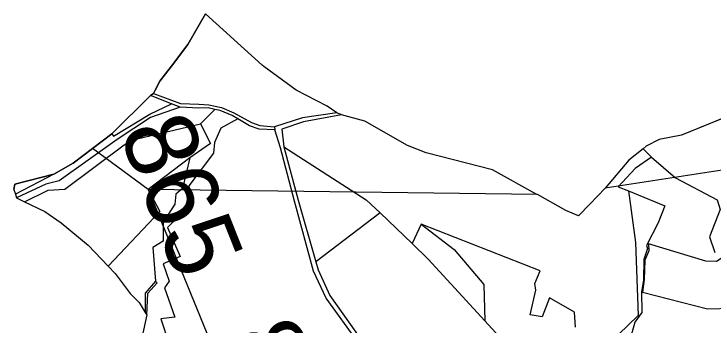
# Model space of a CAD drawing. Extents: x -689422 to -684666, y -987725 to -982160.
# Drawn here: x -689422 to -688518, y -982561 to -982160 of the extents above; entities that cross this region are included whole.
import ezdxf

# ---------------------------------------------------------------- set-up
doc = ezdxf.new("R2010")
doc.units = 0
for name, color, linetype in [('Dalkovy migracni koridor', 7, 'Continuous'), ('Dalkovy migracni koridor popis', 7, 'Continuous'), ('Hranice obce', 7, 'Continuous'), ('KN_Hranice_katastrální území', 7, 'Continuous'), ('KN_hranice_parcel', 7, 'Continuous'), ('Krajina lesozemedelska - 5M2', 7, 'Continuous'), ('Migracne vyznamne uzemi', 7, 'Continuous')]:
    doc.layers.add(name, color=color, linetype=linetype)

msp = doc.modelspace()

# ---------------------------------------------------------------- linework, layer by layer
at = {"layer": 'Dalkovy migracni koridor'}
for p, q in [((-689248.07, -982386.61), (-689320.15, -982333.48)), ((-688745.22, -982393.07), (-689248.07, -982386.61))]:
    msp.add_line(p, q, dxfattribs=at)
for points in [[(-687882.21, -982490.81), (-688366.31, -982339.93), (-688657.8, -982384.57)], [(-689248.07, -982386.61), (-689050.38, -982869.9), (-689019.53, -982977.86), (-688975.65, -983189.91)]]:
    msp.add_lwpolyline(points, dxfattribs=at)
at = {"layer": 'Hranice obce'}
msp.add_lwpolyline([(-688479.99, -982283.8), (-688559.06, -982316.44), (-688587.88, -982321.86), (-688604.6, -982330.69), (-688608.5, -982333.76), (-688627.21, -982348.47), (-688657.8, -982384.57), (-688677.55, -982405.23), (-688692.2, -982420.56), (-688708.5, -982413.35), (-688745.22, -982393.07), (-688745.91, -982392.69), (-688803.08, -982360.91), (-688888.91, -982338.93), (-688912.92, -982329.6), (-688968.34, -982298.26), (-688998.46, -982289.93), (-688998.95, -982289.75), (-689002.89, -982288.29), (-689004.57, -982287.67), (-689016.75, -982279.03), (-689057.02, -982258.22), (-689098.59, -982227.73), (-689100.73, -982225.8), (-689174.07, -982159.87), (-689196.83, -982199.46), (-689218.2, -982227.18), (-689225.83, -982237.08), (-689233.27, -982246.73), (-689239.33, -982258.4), (-689241.08, -982261.77), (-689241.54, -982262.66), (-689245.4, -982264.94), (-689295.33, -982314.65), (-689344.96, -982352.3), (-689370.15, -982366.54), (-689420.52, -982379.61), (-689421.63, -982386.24), (-689419.65, -982392.62), (-689418.16, -982397.39), (-689408.17, -982402.2), (-689381.97, -982414.81), (-689360.72, -982429.64), (-689325.69, -982458.08), (-689299.97, -982485.18), (-689290.84, -982494.81), (-689271.64, -982520.72), (-689259.92, -982532.32), (-689252.18, -982545.1), (-689250.16, -982548.42), (-689263.67, -982611.26)], dxfattribs=at)
at = {"layer": 'KN_Hranice_katastrální území'}
msp.add_lwpolyline([(-688479.99, -982283.8), (-688559.06, -982316.44), (-688587.88, -982321.86), (-688604.6, -982330.69), (-688608.5, -982333.76), (-688627.21, -982348.47), (-688657.8, -982384.57), (-688677.55, -982405.23), (-688692.2, -982420.56), (-688708.5, -982413.35), (-688745.22, -982393.07), (-688745.91, -982392.69), (-688803.08, -982360.91), (-688888.91, -982338.93), (-688912.92, -982329.6), (-688968.34, -982298.26), (-688998.46, -982289.93), (-688998.95, -982289.75), (-689002.89, -982288.29), (-689004.57, -982287.67), (-689016.75, -982279.03), (-689057.02, -982258.22), (-689098.59, -982227.73), (-689100.73, -982225.8), (-689174.07, -982159.87), (-689196.83, -982199.46), (-689218.2, -982227.18), (-689225.83, -982237.08), (-689233.27, -982246.73), (-689239.33, -982258.4), (-689241.08, -982261.77), (-689241.54, -982262.66), (-689245.4, -982264.94), (-689295.33, -982314.65), (-689344.96, -982352.3), (-689370.15, -982366.54), (-689420.52, -982379.61), (-689421.63, -982386.24), (-689419.65, -982392.62), (-689418.16, -982397.39), (-689408.17, -982402.2), (-689381.97, -982414.81), (-689360.72, -982429.64), (-689325.69, -982458.08), (-689299.97, -982485.18), (-689290.84, -982494.81), (-689271.64, -982520.72), (-689259.92, -982532.32), (-689252.18, -982545.1), (-689250.16, -982548.42), (-689263.67, -982611.26)], dxfattribs=at)
at = {"layer": 'KN_hranice_parcel'}
for p, q in [((-689100.73, -982225.8), (-689174.07, -982159.87)), ((-689225.83, -982237.08), (-689218.2, -982227.18)), ((-689295.33, -982314.65), (-689245.4, -982264.94)), ((-689245.4, -982264.94), (-689241.54, -982262.66)), ((-689217.89, -982275.98), (-689245.4, -982264.94)), ((-689241.54, -982262.66), (-689206.31, -982275.42)), ((-689207.09, -982280.31), (-689217.89, -982275.98)), ((-689161.88, -982283.06), (-689180.48, -982301.54)), ((-689161.88, -982283.06), (-689170.73, -982281.16)), ((-689155.06, -982284.52), (-689161.88, -982283.06)), ((-689139.79, -982290.9), (-689155.06, -982284.52)), ((-689002.89, -982288.29), (-689004.57, -982287.67)), ((-688479.99, -982283.8), (-688559.06, -982316.44)), ((-689132.3, -982295.35), (-689139.79, -982290.9)), ((-689117.13, -982304.36), (-689132.3, -982295.35)), ((-688998.95, -982289.75), (-689002.89, -982288.29)), ((-688998.46, -982289.93), (-688998.95, -982289.75)), ((-689085.13, -982305.51), (-689084.54, -982309.35)), ((-689073, -982331.34), (-689054.22, -982400.25)), ((-688604.6, -982330.69), (-688608.5, -982333.76)), ((-688803.08, -982360.91), (-688888.91, -982338.93)), ((-688608.5, -982333.76), (-688597.66, -982344.88)), ((-689420.52, -982379.61), (-689370.15, -982366.54)), ((-689370.15, -982366.54), (-689419.65, -982392.62)), ((-688745.91, -982392.69), (-688803.08, -982360.91)), ((-689421.63, -982386.24), (-689420.52, -982379.61)), ((-689421.63, -982386.24), (-689419.65, -982392.62)), ((-689419.65, -982392.62), (-689418.16, -982397.39)), ((-688745.22, -982393.07), (-688745.91, -982392.69)), ((-688708.5, -982413.35), (-688745.22, -982393.07)), ((-689418.16, -982397.39), (-689408.17, -982402.2)), ((-689408.17, -982402.2), (-689381.97, -982414.81)), ((-689054.22, -982400.25), (-689031.44, -982479.99)), ((-688677.55, -982405.23), (-688692.2, -982420.56)), ((-688692.2, -982420.56), (-688708.5, -982413.35)), ((-688948.64, -982416.69), (-689031.44, -982479.99)), ((-688907.18, -982456.28), (-688948.64, -982416.69)), ((-688895.28, -982431), (-688907.18, -982456.28)), ((-689325.69, -982458.08), (-689299.97, -982485.18)), ((-689299.97, -982485.18), (-689290.84, -982494.81)), ((-689031.44, -982479.99), (-689028.56, -982490.08)), ((-688609.32, -982518.77), (-688610.88, -982518.36)), ((-689252.18, -982545.1), (-689250.16, -982548.42)), ((-688813.31, -982555.94), (-688794.65, -982576.32))]:
    msp.add_line(p, q, dxfattribs=at)
for points in [[(-689218.2, -982227.18), (-689196.83, -982199.46), (-689174.07, -982159.87)], [(-689004.57, -982287.67), (-689016.75, -982279.03), (-689057.02, -982258.22), (-689098.59, -982227.73), (-689100.73, -982225.8)], [(-689241.54, -982262.66), (-689241.08, -982261.77), (-689239.33, -982258.4), (-689233.27, -982246.73), (-689225.83, -982237.08)], [(-689295.33, -982314.65), (-689293.24, -982317.45), (-689246.03, -982289.03), (-689217.89, -982275.98)], [(-689206.31, -982275.42), (-689182.81, -982276.06), (-689169.97, -982277.14), (-689153.67, -982280.7), (-689137.74, -982287.53), (-689114.61, -982300.04), (-689104.07, -982303.87), (-689085.13, -982305.51)], [(-689207.09, -982280.31), (-689245.09, -982293.55), (-689288.16, -982322.06), (-689363.24, -982375.02), (-689380.54, -982379.72), (-689418.16, -982397.39)], [(-689170.73, -982281.16), (-689182.68, -982281.37), (-689207.09, -982280.31)], [(-689004.57, -982287.67), (-689048.75, -982293.75), (-689085.13, -982305.51)], [(-689132.3, -982295.35), (-689154.31, -982307.35), (-689162.48, -982325.88), (-689163.75, -982339.5), (-689195.48, -982381.69), (-689192.3, -982404.85), (-689223.24, -982435.28), (-689206.97, -982472.82), (-689228.68, -982482.32), (-689220.91, -982504.84), (-689227.09, -982513.18), (-689213.95, -982551.11), (-689232.01, -982553.5), (-689220.98, -982586.19), (-689240.9, -982594.56), (-689221.33, -982611.7), (-689223.53, -982619.27), (-689246.1, -982624.55), (-689245.3, -982634.52), (-689249.68, -982633.19), (-689261.24, -982663.02), (-689260.84, -982684.68), (-689274.91, -982699.36), (-689277.87, -982740.23)], [(-688998.46, -982289.93), (-689047.38, -982299.22), (-689075.47, -982308.44), (-689073, -982331.34)], [(-688888.91, -982338.93), (-688912.92, -982329.6), (-688968.34, -982298.26), (-688998.46, -982289.93)], [(-689408.17, -982402.2), (-689377.35, -982387.34), (-689355.91, -982386.12), (-689279.13, -982328.6), (-689269.78, -982322.86), (-689180.48, -982301.54)], [(-689180.48, -982301.54), (-689167.75, -982327.17), (-689194.19, -982345.72)], [(-689084.54, -982309.35), (-689104.97, -982308.38), (-689117.13, -982304.36)], [(-689370.15, -982366.54), (-689344.96, -982352.3), (-689295.33, -982314.65)], [(-688976.63, -982584.53), (-689018.36, -982526.75), (-689034.37, -982491.83), (-689059.15, -982401.37), (-689077.12, -982332.65), (-689084.54, -982309.35)], [(-688559.06, -982316.44), (-688587.88, -982321.86), (-688604.6, -982330.69)], [(-689073, -982331.34), (-688966.58, -982399.56), (-688948.64, -982416.69)], [(-688608.5, -982333.76), (-688627.21, -982348.47), (-688657.8, -982384.57), (-688677.55, -982405.23)], [(-689194.19, -982345.72), (-689248.07, -982386.61), (-689233.02, -982414.94), (-689299.97, -982485.18)], [(-689194.19, -982345.72), (-689203.78, -982385.28), (-689212.44, -982392.62), (-689213.75, -982405.41), (-689228.69, -982428.58), (-689228.69, -982453.33), (-689242.33, -982461.21), (-689238.58, -982504.84)], [(-688597.66, -982344.88), (-688618.84, -982359.45), (-688640.87, -982382.91), (-688627.65, -982388.34)], [(-688597.66, -982344.88), (-688566.97, -982371.29), (-688513.06, -982399.73), (-688509.01, -982412.35), (-688522.88, -982447.63), (-688515.82, -982467.85)], [(-688627.65, -982388.34), (-688618.63, -982454.89), (-688614.92, -982548.98), (-688653.05, -982585.47)], [(-688627.65, -982388.34), (-688580.78, -982407.61), (-688589.37, -982429.54), (-688604.21, -982458.53), (-688602.8, -982462.69), (-688607.54, -982476.96), (-688608.21, -982503.08), (-688610.88, -982518.36)], [(-689381.97, -982414.81), (-689360.72, -982429.64), (-689325.69, -982458.08)], [(-688895.28, -982431), (-688852.67, -982463.96), (-688814.61, -982508.87), (-688813.31, -982555.94)], [(-688696.12, -982564.1), (-688697.51, -982544.63), (-688729.55, -982526.44), (-688738.92, -982550.91), (-688754.73, -982548.13), (-688747.12, -982516.55), (-688748.58, -982507.91), (-688741.7, -982491.57), (-688895.28, -982431)], [(-688907.18, -982456.28), (-688886.34, -982476.18), (-688813.31, -982555.94)], [(-688447.14, -982508.24), (-688448.12, -982491.82), (-688462.64, -982460.26), (-688483.68, -982459.74), (-688513.67, -982479.19), (-688527.78, -982479.06), (-688601.69, -982456.52), (-688601.17, -982465.72), (-688606.21, -982477.63), (-688607.32, -982502.64), (-688609.32, -982518.77)], [(-689290.84, -982494.81), (-689271.64, -982520.72), (-689259.92, -982532.32), (-689252.18, -982545.1)], [(-689028.56, -982490.08), (-689013.39, -982523.42), (-688972.41, -982581.04), (-688935.15, -982614.73), (-688912.49, -982642.6), (-688867.24, -982688.32)], [(-689238.58, -982504.84), (-689252.12, -982520.12), (-689252.18, -982545.1)], [(-689250.16, -982548.42), (-689248.81, -982520.39), (-689236.72, -982506.7), (-689238.58, -982504.84)], [(-688610.88, -982518.36), (-688610.23, -982545.07), (-688619.41, -982557.77), (-688632.32, -982604.47)], [(-688609.32, -982518.77), (-688525.48, -982540.51), (-688494.01, -982539.74)], [(-689250.16, -982548.42), (-689263.67, -982611.26), (-689261.99, -982634.29), (-689268.82, -982654.64)]]:
    msp.add_lwpolyline(points, dxfattribs=at)
at = {"layer": 'Krajina lesozemedelska - 5M2'}
msp.add_lwpolyline([(-688479.99, -982283.8), (-688559.06, -982316.44), (-688587.88, -982321.86), (-688604.6, -982330.69), (-688608.5, -982333.76), (-688627.21, -982348.47), (-688657.8, -982384.57), (-688677.55, -982405.23), (-688692.2, -982420.56), (-688708.5, -982413.35), (-688745.22, -982393.07), (-688745.91, -982392.69), (-688803.08, -982360.91), (-688888.91, -982338.93), (-688912.92, -982329.6), (-688968.34, -982298.26), (-688998.46, -982289.93), (-688998.95, -982289.75), (-689002.89, -982288.29), (-689004.57, -982287.67), (-689016.75, -982279.03), (-689057.02, -982258.22), (-689098.59, -982227.73), (-689100.73, -982225.8), (-689174.07, -982159.87), (-689196.83, -982199.46), (-689218.2, -982227.18), (-689225.83, -982237.08), (-689233.27, -982246.73), (-689239.33, -982258.4), (-689241.08, -982261.77), (-689241.54, -982262.66), (-689245.4, -982264.94), (-689295.33, -982314.65), (-689344.96, -982352.3), (-689370.15, -982366.54), (-689420.52, -982379.61), (-689421.63, -982386.24), (-689419.65, -982392.62), (-689418.16, -982397.39), (-689408.17, -982402.2), (-689381.97, -982414.81), (-689360.72, -982429.64), (-689325.69, -982458.08), (-689299.97, -982485.18), (-689290.84, -982494.81), (-689271.64, -982520.72), (-689259.92, -982532.32), (-689252.18, -982545.1), (-689250.16, -982548.42), (-689263.67, -982611.26)], dxfattribs=at)
at = {"layer": 'Migracne vyznamne uzemi'}
msp.add_lwpolyline([(-688479.99, -982283.8), (-688559.06, -982316.44), (-688587.88, -982321.86), (-688604.6, -982330.69), (-688608.5, -982333.76), (-688627.21, -982348.47), (-688657.8, -982384.57), (-688677.55, -982405.23), (-688692.2, -982420.56), (-688708.5, -982413.35), (-688745.22, -982393.07), (-688745.91, -982392.69), (-688803.08, -982360.91), (-688888.91, -982338.93), (-688912.92, -982329.6), (-688968.34, -982298.26), (-688998.46, -982289.93), (-688998.95, -982289.75), (-689002.89, -982288.29), (-689004.57, -982287.67), (-689016.75, -982279.03), (-689057.02, -982258.22), (-689098.59, -982227.73), (-689100.73, -982225.8), (-689174.07, -982159.87), (-689196.83, -982199.46), (-689218.2, -982227.18), (-689225.83, -982237.08), (-689233.27, -982246.73), (-689239.33, -982258.4), (-689241.08, -982261.77), (-689241.54, -982262.66), (-689245.4, -982264.94), (-689295.33, -982314.65), (-689344.96, -982352.3), (-689370.15, -982366.54), (-689420.52, -982379.61), (-689421.63, -982386.24), (-689419.65, -982392.62), (-689418.16, -982397.39), (-689408.17, -982402.2), (-689381.97, -982414.81), (-689360.72, -982429.64), (-689325.69, -982458.08), (-689299.97, -982485.18), (-689290.84, -982494.81), (-689271.64, -982520.72), (-689259.92, -982532.32), (-689252.18, -982545.1), (-689250.16, -982548.42), (-689263.67, -982611.26)], dxfattribs=at)

# ---------------------------------------------------------------- texts
at = {"layer": 'Dalkovy migracni koridor popis'}
for s, p in [('865', (-689286.56, -982312.86)), ('846', (-689147.91, -982577.22))]:
    msp.add_text(s, height=93.75, rotation=291.62985, dxfattribs=at).set_placement(p)

doc.saveas('drawing.dxf')
